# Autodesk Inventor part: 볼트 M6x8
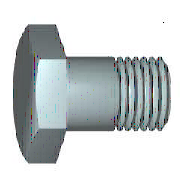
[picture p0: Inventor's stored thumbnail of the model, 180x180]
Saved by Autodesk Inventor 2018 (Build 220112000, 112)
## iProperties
Created: 2012-02
Part Number: 볼트 M6x8
Material: 강철, 연강
Description: 6각 머리 볼트 및 6각 머리 나사
Document SubType Name: Modeling
Standard: KS B 1002
Designer: mduedu
Standards Organization: KS
Language: ko-KR
Size Designation: C  M 6 x 12
Categories: <MemberInstance><Categories><Category DisplayName="조임쇠" InternalName="e4da775c-781d-43d5-af7c-5136215cf5a6" Mnemonic="FSTN"><Category DisplayName="볼트" InternalN
Density: 1 g/cm^3
Appearance: 강철
IsCustomPart: 1
Author: mduedu
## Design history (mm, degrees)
sketch "스케치1"
  geometry: L1 (0, 3)-(8, 3); L2 (8, 3)-(8, 0); L3 (8, 0)-(0, 0); L4 (-2.4, 0)-(14.4, 0) reference; L5 (0, -0.6)-(0, 3.6) reference; L6 (0, 3)-(0, 0)
  constraints: 8 end point, 3 point on line, 1 collinear
  dimensions: "d2" = 6 diameter of L1 L3 (= GD); "d59" = 8 distance between parallel lines of L2 L5 (= NLG)
revolve "본체" sketch "스케치1" stored, may be unused: angle "d12" = 90 deg
sketch "스케치2"
  geometry: L1 (0, 5.774)-(5, 2.887); L2 (5, 2.887)-(5, -2.887); L3 (5, -2.887)-(0, -5.774); L4 (0, -5.774)-(-5, -2.887); L5 (-5, -2.887)-(-5, 2.887); L6 (-5, 2.887)-(0, 5.774); L7 (-7, 0)-(7, 0) reference; L8 (0, 8.083)-(0, -8.083) reference; 2 further points
  constraints: 12 end point, 2 midpoint, 1 coincident, 1 vertical, 11 other
  dimensions: "d11" = 10 distance between parallel lines of L5 L2 (= SW)
extrude "머리" join sketch "스케치2" distance "d3" = 4 (= KOH); taper "d4" = 0 deg
revolve "모따기1" stored, may be unused: angle "d21" = 90 deg
workplane "Work Plane1"
body "Solid1"
feature "스레드" dims "d15" = 9 (= GEL), "d16" = 0
chamfer "모따기2" distance "d6" = 0.61345 (= -0.5 x SPD + 0.5 x GD); stored, may be unused: second distance "d7" = 0.61355 (computed from GUL), angle "d55" = 45 deg
sketch "스케치4"
  geometry: L1 (-3.423, 6)-(-4, 5); L2 (-1.1, 0)-(-0.234, 0); L3 (-4.753, 0)-(0.519, 0) reference; L4 (-4, 6)-(-3.423, 6); L5 (-4, 5)-(-4, 6); L6 (0, 7.2)-(0, -1.2) reference
  constraints: 8 end point, 1 parallel, 1 perpendicular, 1 point on line
  dimensions: "d65" = 10 diameter of L1.end L2 (= SW); "d67" = 30 deg angle of L1 L5 (= ANG1); "d68" = 12 diameter of L4 L2 (= 1.2 x SW); "d69" = 4 distance between parallel lines of L5 L6 (= KOH)
other parameters: "NLG" = 8 [user parameter; used in 1 equation term], "GD" = 6 (= NND) [user parameter; used in 2 equation terms], "BDM" = 6 (= NND) [user parameter], "KOH" = 4 [user parameter; used in 2 equation terms], "GEL" = 9 [user parameter; used in 1 equation term], "SW" = 10 [user parameter; used in 5 equation terms], "SPD" = 4.7731 (= NND - 1.2269 x PTC) [user parameter; used in 1 equation term], "SD2" = 6 (= NND) [user parameter], "SD" = 0 [user parameter], "ANG1" = 30 deg [user parameter; used in 1 equation term], "GAL" = 0.61345 (= 0.61345 x PTC) [user parameter], "GUL" = 0.61345 (= 0.61345 x PTC) [user parameter; used in 1 equation term], "d8" = 0, "RR" = 0.25 [user parameter], "d58" = 0, "RR1" = 0.1 [user parameter], "GD1" = 4.7731 (= THREADDIA - 1.2269 x PTC) [user parameter], "THREADDIA" = 6 [user parameter; used in 1 equation term], "TOA" = 30 deg [user parameter], "PTC" = 1 [user parameter; used in 5 equation terms], "NND" = 6 [user parameter; used in 4 equation terms], "E0" = 11.55 (= 1.155 x SW) [user parameter]
